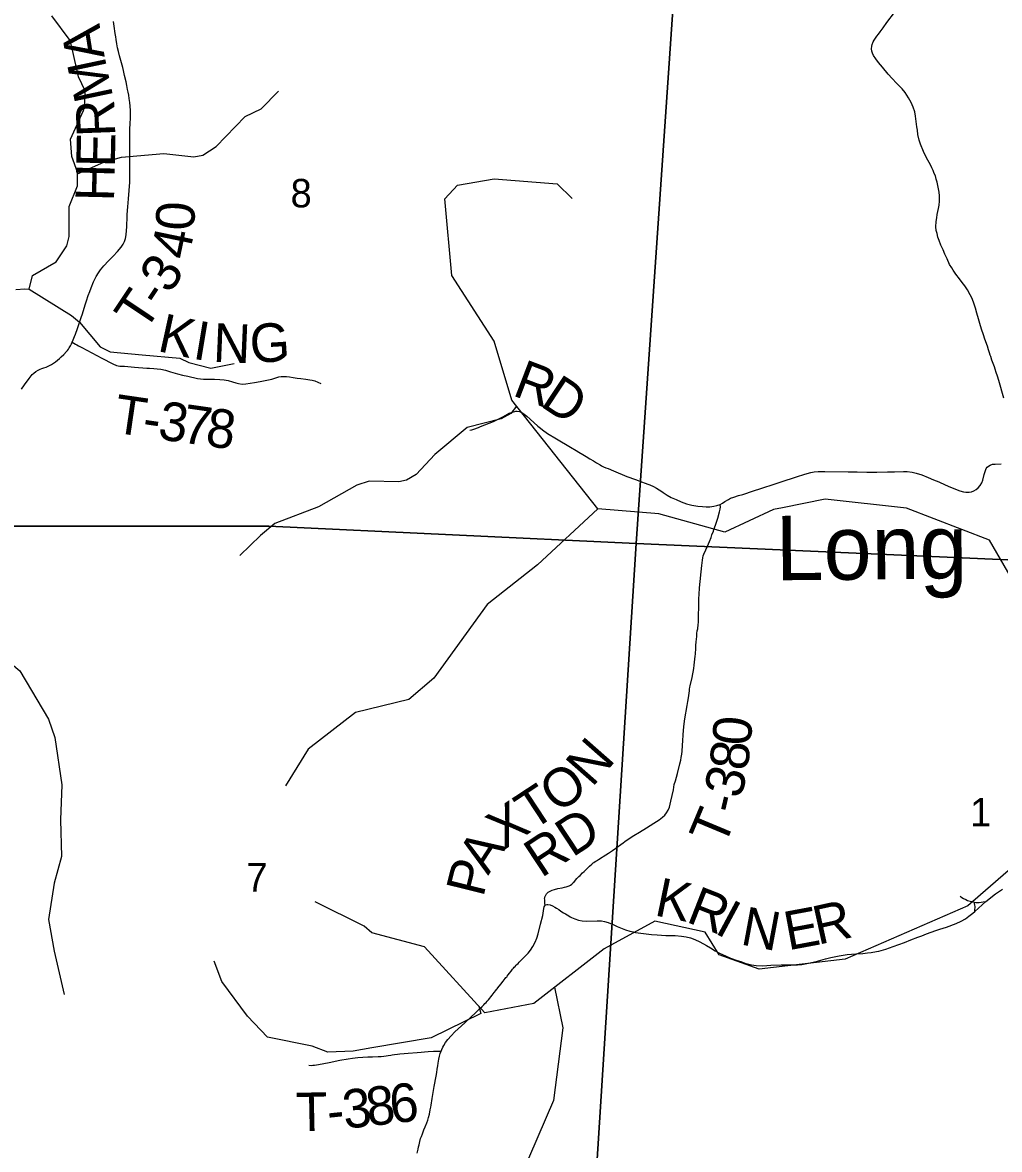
# Model space of a CAD drawing. Extents: x 21.4 to 65.3, y 4 to 26.
# Drawn here: x 24.436 to 25.873, y 20.591 to 22.248 of the extents above; entities that cross this region are included whole.
import ezdxf

# ---------------------------------------------------------------- set-up
doc = ezdxf.new("R2010")
doc.units = 0
for name, color, linetype in [('GM_X_County_Road', 7, 'Continuous'), ('GM_X_County_Road_Text', 7, 'Continuous'), ('GM_X_Minor_River', 7, 'Continuous'), ('GM_X_Minor_River_Text', 7, 'Continuous'), ('GM_X_Section', 7, 'Continuous'), ('GM_X_Section_Text', 7, 'Continuous'), ('GM_X_Township_Road', 7, 'Continuous'), ('GM_X_Township_Road_Text', 7, 'Continuous')]:
    doc.layers.add(name, color=color, linetype=linetype)

msp = doc.modelspace()

# ---------------------------------------------------------------- linework, layer by layer
at = {"layer": 'GM_X_County_Road'}
for points in [[(25.879, 21.6955), (25.8716, 21.7216), (25.8696, 21.7279), (25.8679, 21.7334), (25.8663, 21.7381), (25.8651, 21.7416), (25.8616, 21.7515), (25.8598, 21.7567), (25.8589, 21.759), (25.8577, 21.7625), (25.8563, 21.7666), (25.8548, 21.772), (25.851, 21.7823), (25.8489, 21.7887), (25.8462, 21.7969), (25.8437, 21.8055), (25.8419, 21.8121), (25.8393, 21.8208), (25.8372, 21.8281), (25.8344, 21.837), (25.832, 21.843), (25.8297, 21.8478), (25.8255, 21.8552), (25.8216, 21.861), (25.8179, 21.8656), (25.8136, 21.8713), (25.8084, 21.878), (25.8045, 21.8838), (25.8024, 21.8872), (25.7993, 21.8922), (25.7955, 21.9004), (25.7923, 21.9075), (25.7897, 21.9138), (25.7865, 21.9205), (25.7837, 21.9276), (25.7822, 21.9324), (25.7808, 21.9376), (25.7795, 21.9424), (25.7791, 21.9478), (25.7794, 21.9555), (25.7803, 21.9611), (25.7811, 21.9659), (25.782, 21.9701), (25.7829, 21.9747), (25.7837, 21.9795), (25.7842, 21.9853), (25.7842, 21.9931), (25.7838, 21.9986), (25.7827, 22.0062), (25.7808, 22.0133), (25.7797, 22.0175), (25.7783, 22.0224), (25.7768, 22.0262), (25.7753, 22.0303), (25.7732, 22.0343), (25.771, 22.0388), (25.7651, 22.0492), (25.7608, 22.0582), (25.7563, 22.0692), (25.7546, 22.0753), (25.7528, 22.0834), (25.7519, 22.0898), (25.7511, 22.0947), (25.7502, 22.1027), (25.7492, 22.1105), (25.748, 22.1168), (25.7459, 22.1236), (25.7428, 22.1306), (25.739, 22.1375), (25.7339, 22.1453), (25.7294, 22.1505), (25.7252, 22.1551), (25.7214, 22.1591), (25.715, 22.1659), (25.7091, 22.1723), (25.7007, 22.1822), (25.6948, 22.1894), (25.6906, 22.1948), (25.6874, 22.1996), (25.6857, 22.203), (25.6848, 22.2062), (25.6844, 22.2094), (25.6847, 22.2132), (25.6853, 22.2157), (25.6869, 22.2199), (25.6882, 22.2221), (25.6905, 22.2251), (25.6924, 22.2279), (25.6949, 22.231), (25.6972, 22.2345), (25.7017, 22.2405), (25.7072, 22.2481), (25.7183, 22.2629)], [(25.8363, 20.941), (25.8527, 20.9555), (25.8666, 20.9666), (25.877, 20.9734)], [(25.0517, 20.7355), (25.0528, 20.738), (25.0542, 20.7413), (25.0555, 20.7439), (25.058, 20.7482), (25.0614, 20.7524), (25.0665, 20.7581), (25.0717, 20.7637), (25.0864, 20.7768), (25.095, 20.7849), (25.1026, 20.792), (25.1083, 20.7976), (25.1119, 20.8012), (25.1145, 20.8037), (25.1161, 20.8054), (25.1177, 20.8071), (25.1193, 20.8088), (25.1204, 20.8101), (25.1212, 20.8109), (25.1231, 20.8131), (25.125, 20.8155), (25.1269, 20.8178), (25.1299, 20.8216), (25.1322, 20.8245), (25.1333, 20.826), (25.134, 20.8269), (25.1352, 20.8283), (25.1397, 20.834), (25.1429, 20.8384), (25.1459, 20.8421), (25.147, 20.8435), (25.1481, 20.8449), (25.1488, 20.8459), (25.1501, 20.8477), (25.1522, 20.8503), (25.1545, 20.8532), (25.1557, 20.8545), (25.1568, 20.8559), (25.1581, 20.8573), (25.1593, 20.8587), (25.1606, 20.86), (25.1622, 20.8618), (25.1631, 20.8627), (25.1648, 20.8644), (25.1666, 20.8662), (25.1703, 20.8701), (25.1749, 20.8747), (25.1795, 20.8796), (25.1832, 20.8839), (25.1866, 20.8891), (25.1898, 20.8956), (25.1923, 20.9017), (25.1944, 20.9081), (25.1979, 20.922), (25.2011, 20.935), (25.2029, 20.9452), (25.2034, 20.9477), (25.204, 20.9492), (25.2046, 20.9498)], [(25.2046, 20.9498), (25.2053, 20.9504), (25.2069, 20.9509), (25.2088, 20.9511), (25.212, 20.9505), (25.2156, 20.9489), (25.2188, 20.9472), (25.2215, 20.9457), (25.2246, 20.9436), (25.2279, 20.9413), (25.2318, 20.939), (25.2346, 20.9373), (25.2393, 20.9342), (25.2414, 20.9329), (25.2436, 20.9318), (25.2482, 20.9298), (25.2535, 20.9281), (25.2589, 20.9271), (25.2655, 20.9267), (25.2811, 20.9271), (25.2875, 20.9268), (25.2921, 20.9261), (25.2972, 20.9246), (25.3055, 20.9212), (25.3104, 20.9188), (25.3152, 20.9167), (25.3226, 20.9136), (25.3291, 20.9118), (25.3338, 20.9108), (25.3377, 20.9099), (25.3453, 20.9088), (25.3529, 20.9078), (25.361, 20.907), (25.3693, 20.9063), (25.3758, 20.9058), (25.382, 20.9056), (25.3879, 20.9054), (25.3958, 20.9053), (25.4049, 20.9045), (25.4121, 20.9036), (25.4185, 20.9019), (25.4248, 20.8996), (25.432, 20.8961), (25.4418, 20.8907), (25.4476, 20.8873), (25.4547, 20.8831), (25.4611, 20.8796), (25.4697, 20.8755), (25.4771, 20.8722), (25.4868, 20.8686), (25.4921, 20.867), (25.4983, 20.865), (25.508, 20.8624), (25.5148, 20.8615), (25.5248, 20.8611), (25.5366, 20.8616), (25.5515, 20.8622), (25.557, 20.8623), (25.5682, 20.8621), (25.5757, 20.8622), (25.5819, 20.8629), (25.5917, 20.8647), (25.605, 20.8679), (25.6098, 20.8693), (25.6167, 20.8711), (25.6248, 20.8732), (25.6369, 20.8757), (25.6488, 20.8774), (25.6612, 20.8783), (25.6719, 20.8791), (25.6787, 20.8798), (25.6841, 20.8803), (25.6916, 20.8819), (25.695, 20.8826), (25.7054, 20.8856), (25.7164, 20.8892), (25.7328, 20.8953), (25.7425, 20.899), (25.7525, 20.9029), (25.7584, 20.9052), (25.7655, 20.9078), (25.7724, 20.9105), (25.7792, 20.9128), (25.785, 20.9148), (25.7948, 20.9179), (25.809, 20.9232), (25.8163, 20.9264), (25.8226, 20.9302), (25.8275, 20.9337), (25.8333, 20.9384), (25.8363, 20.941)], [(25.0167, 20.5856), (25.0178, 20.5911), (25.0185, 20.5945), (25.0192, 20.5977), (25.0205, 20.6025), (25.0216, 20.6067), (25.0228, 20.6101), (25.0241, 20.6137), (25.0264, 20.6195), (25.0282, 20.6243), (25.0307, 20.6301), (25.0321, 20.6338), (25.0331, 20.6376), (25.0345, 20.6427), (25.0358, 20.6489), (25.0364, 20.6528), (25.0369, 20.656), (25.0385, 20.6656), (25.0413, 20.6832), (25.0442, 20.6987), (25.0452, 20.7041), (25.0459, 20.7091), (25.0468, 20.7138), (25.0475, 20.7179), (25.0485, 20.7237), (25.0494, 20.7279), (25.0505, 20.7318), (25.0517, 20.7355)]]:
    msp.add_lwpolyline(points, dxfattribs=at)
at = {"layer": 'GM_X_Minor_River'}
for points in [[(24.4265, 21.8553), (24.4398, 21.8565), (24.4462, 21.8561), (24.4511, 21.8759), (24.4856, 21.8961), (24.5012, 21.9197), (24.5046, 21.9334), (24.505, 21.9775), (24.5171, 22.0079), (24.5171, 22.028), (24.5088, 22.0512), (24.5069, 22.0767), (24.5259, 22.1189), (24.5278, 22.1254), (24.5282, 22.1474), (24.5187, 22.168), (24.5093, 22.2098), (24.5062, 22.2216), (24.4793, 22.258)], [(24.5171, 22.0254), (24.5556, 22.0428), (24.5819, 22.05), (24.6439, 22.0553), (24.6883, 22.0505), (24.7012, 22.053), (24.7211, 22.0656), (24.7636, 22.1099), (24.7869, 22.121), (24.8127, 22.1472)], [(25.2821, 21.5328), (25.1557, 21.6926), (25.1299, 21.7797), (25.0675, 21.8759), (25.0569, 21.9889), (25.0757, 22.0088), (25.1298, 22.0184), (25.2225, 22.0109), (25.2445, 21.9894)], [(24.4462, 21.8561), (24.5083, 21.817), (24.5199, 21.8073), (24.5506, 21.7711), (24.5649, 21.7637), (24.612, 21.7593), (24.6673, 21.7547), (24.6809, 21.7481), (24.7131, 21.74), (24.7474, 21.7468)], [(25.1627, 21.6838), (25.1543, 21.6732), (25.1401, 21.6654), (25.0898, 21.6524), (25.0422, 21.6128), (25.0152, 21.5835), (25.001, 21.575), (24.9895, 21.5725), (24.9459, 21.5738), (24.9279, 21.5676), (24.8716, 21.5361), (24.8071, 21.5115), (24.7863, 21.4939), (24.7559, 21.4643)], [(25.8903, 21.4308), (25.8577, 21.4867), (25.736, 21.5338), (25.6162, 21.5471), (25.5534, 21.5344), (25.5405, 21.5317), (25.4688, 21.4988), (25.372, 21.5256), (25.282, 21.5328), (25.1935, 21.4504), (25.1194, 21.3924), (25.0412, 21.2839), (25.0044, 21.2525), (24.926, 21.2335), (24.8561, 21.1794), (24.823, 21.1256)], [(24.3346, 21.3102), (24.3759, 21.3218), (24.4202, 21.3048), (24.4323, 21.2949), (24.4744, 21.2238), (24.4835, 21.1965), (24.4941, 21.1269), (24.4922, 21.0756), (24.4937, 21.0216), (24.483, 20.9824), (24.4743, 20.9292), (24.4826, 20.8824), (24.4974, 20.8189)], [(26.1634, 21.1477), (26.0593, 21.1142), (25.9946, 21.0666), (25.9113, 21.0233), (25.8261, 20.9493), (25.6456, 20.8706), (25.5194, 20.8558), (25.4603, 20.877), (25.4397, 20.9106), (25.3659, 20.9266), (25.2916, 20.8861), (25.1879, 20.8054), (25.1159, 20.7919), (25.027, 20.889), (24.95, 20.9096), (24.9385, 20.919), (24.8667, 20.9548)], [(25.1071, 20.8015), (25.1103, 20.7906), (25.0372, 20.7548), (24.9496, 20.7404), (24.9222, 20.7354), (24.8853, 20.734), (24.8623, 20.7427), (24.7964, 20.7562), (24.7672, 20.787), (24.7292, 20.8376), (24.7182, 20.8678)], [(25.2185, 20.8293), (25.2305, 20.7698), (25.2167, 20.663), (25.1342, 20.4706), (25.1208, 20.42)]]:
    msp.add_lwpolyline(points, dxfattribs=at)
at = {"layer": 'GM_X_Section'}
for points in [[(24.3505, 22.5376), (24.828, 22.5152), (25.4085, 22.5025), (25.3384, 21.4821), (24.7985, 21.5074), (24.2858, 21.5075), (24.3136, 21.9252), (24.3404, 22.3383)], [(25.4085, 22.5025), (26.4597, 22.4573), (26.4491, 22.292), (26.4111, 21.6607), (26.3977, 21.4352), (25.3384, 21.4821)], [(25.3384, 21.4821), (25.275, 20.4836), (24.2227, 20.5192), (24.2858, 21.5075), (24.7985, 21.5074)], [(26.3977, 21.4352), (26.3809, 21.1738), (26.3352, 20.4317), (25.2871, 20.4832), (25.275, 20.4836), (25.3384, 21.4821)]]:
    msp.add_lwpolyline(points, close=True, dxfattribs=at)
at = {"layer": 'GM_X_Township_Road'}
for points in [[(24.4349, 21.7091), (24.4393, 21.7151), (24.446, 21.7247), (24.4506, 21.7304), (24.4529, 21.7326), (24.4556, 21.7347), (24.4593, 21.7368), (24.4621, 21.7381), (24.4645, 21.7393), (24.4677, 21.7405), (24.4708, 21.7413), (24.4751, 21.7433), (24.4788, 21.7453), (24.4847, 21.7489), (24.4878, 21.7516), (24.4905, 21.754), (24.4932, 21.7565), (24.497, 21.7599), (24.501, 21.7644), (24.5023, 21.7659), (24.5039, 21.7678), (24.505, 21.7696), (24.5067, 21.7725), (24.5083, 21.7757), (24.5092, 21.7778), (24.5108, 21.7813), (24.5127, 21.7864), (24.514, 21.7899), (24.517, 21.7981), (24.5207, 21.8086), (24.5226, 21.8144), (24.5244, 21.8198), (24.5283, 21.8329), (24.5303, 21.839), (24.5327, 21.8464), (24.535, 21.8525), (24.5371, 21.858), (24.5407, 21.8666), (24.5444, 21.8744), (24.5478, 21.8802), (24.5507, 21.8842), (24.5558, 21.8904), (24.5625, 21.8977), (24.5695, 21.9047), (24.5759, 21.9114), (24.5811, 21.9177), (24.5842, 21.9223), (24.5862, 21.9262), (24.5876, 21.9304), (24.5885, 21.936), (24.5892, 21.9422), (24.5895, 21.9474), (24.5897, 21.9527), (24.59, 21.9583), (24.5901, 21.9626), (24.5903, 21.9651), (24.5908, 21.9714), (24.5912, 21.9768), (24.592, 21.9889), (24.5938, 22.0132), (24.5942, 22.0334), (24.5942, 22.0402), (24.594, 22.0506), (24.5939, 22.0543), (24.5938, 22.0648), (24.5939, 22.0822), (24.5941, 22.0909), (24.5945, 22.1001), (24.595, 22.1068), (24.5952, 22.1123), (24.595, 22.1187), (24.5946, 22.1252), (24.5941, 22.1307), (24.5931, 22.1362), (24.5924, 22.1411), (24.5914, 22.1459), (24.5907, 22.1496), (24.5896, 22.1557), (24.5885, 22.1611), (24.5863, 22.1704), (24.5847, 22.1775), (24.5836, 22.1821), (24.5828, 22.1855), (24.5788, 22.1989), (24.5771, 22.2056), (24.5759, 22.211), (24.5749, 22.2165), (24.5738, 22.2232), (24.5732, 22.2268), (24.5726, 22.2318), (24.5711, 22.2426), (24.5702, 22.2495)], [(24.5092, 21.7778), (24.5143, 21.7751), (24.5159, 21.7743), (24.5185, 21.7728), (24.5234, 21.7702), (24.5381, 21.7622), (24.5526, 21.7547), (24.5688, 21.7462), (24.5746, 21.7438), (24.5792, 21.7429), (24.5861, 21.7425), (24.601, 21.7411), (24.6189, 21.7399), (24.6227, 21.7397), (24.6293, 21.7392), (24.634, 21.7387), (24.6397, 21.7381), (24.6463, 21.7368), (24.654, 21.7346), (24.6642, 21.7315), (24.6712, 21.7295), (24.6795, 21.7281), (24.6935, 21.7248), (24.7024, 21.7235), (24.7103, 21.7234), (24.7186, 21.7234), (24.7264, 21.7232), (24.7327, 21.7227), (24.7384, 21.7216), (24.7451, 21.7196), (24.7498, 21.7182), (24.7539, 21.7173), (24.7591, 21.7164), (24.7647, 21.7167), (24.7708, 21.7175), (24.7775, 21.7188), (24.7856, 21.7201), (24.7952, 21.7221), (24.8028, 21.7238), (24.8085, 21.7255), (24.8133, 21.7268), (24.8166, 21.7274), (24.82, 21.7277), (24.8245, 21.7274), (24.8289, 21.7268), (24.8343, 21.726), (24.8398, 21.7252), (24.8456, 21.7244), (24.8529, 21.7235), (24.8585, 21.7227), (24.8622, 21.7221), (24.8658, 21.7211), (24.8704, 21.7194), (24.875, 21.7173)], [(25.0941, 21.6485), (25.097, 21.6491), (25.1, 21.65), (25.1064, 21.6525), (25.1097, 21.6538), (25.1288, 21.6615), (25.1432, 21.6687), (25.1519, 21.6735), (25.1565, 21.6753), (25.1613, 21.6765), (25.1637, 21.6767), (25.1667, 21.676), (25.1702, 21.6746), (25.174, 21.6722), (25.1779, 21.6691), (25.1825, 21.6649), (25.1939, 21.6544), (25.1978, 21.6513), (25.2007, 21.6489), (25.2083, 21.6436), (25.2211, 21.636), (25.2419, 21.6236), (25.25, 21.6189), (25.2542, 21.6164), (25.26, 21.613), (25.2649, 21.6101), (25.2704, 21.6066), (25.2757, 21.6033), (25.2801, 21.6005), (25.2854, 21.5974), (25.2877, 21.5962), (25.2903, 21.5948), (25.2937, 21.5934), (25.2972, 21.592), (25.3052, 21.5886), (25.3247, 21.5807), (25.3375, 21.576), (25.3462, 21.5728), (25.3515, 21.5708), (25.3555, 21.5693), (25.3584, 21.5682), (25.3641, 21.5659), (25.3685, 21.5635), (25.3721, 21.5611), (25.3745, 21.5594), (25.3782, 21.5567), (25.3839, 21.553), (25.3899, 21.5498), (25.3974, 21.5465), (25.4045, 21.5433), (25.4125, 21.5403), (25.4203, 21.5385), (25.4289, 21.537), (25.4361, 21.5363), (25.4414, 21.536), (25.4466, 21.5361), (25.4525, 21.5369), (25.4572, 21.538), (25.4619, 21.5395)], [(25.4619, 21.5395), (25.4655, 21.5413), (25.469, 21.5435), (25.474, 21.5466), (25.4772, 21.5484), (25.4818, 21.5501), (25.4888, 21.5523), (25.4953, 21.5542), (25.4995, 21.5555), (25.5066, 21.5577), (25.5125, 21.5597), (25.5201, 21.5622), (25.5443, 21.5703), (25.5514, 21.5726), (25.5744, 21.58), (25.5863, 21.5838), (25.5951, 21.5865), (25.5999, 21.5874), (25.606, 21.5878), (25.6159, 21.5879), (25.6501, 21.5874), (25.6632, 21.5872), (25.6774, 21.5869), (25.6923, 21.5868), (25.7079, 21.5871), (25.7183, 21.5874), (25.7315, 21.5878), (25.737, 21.5876), (25.7443, 21.5867), (25.7503, 21.5853), (25.7586, 21.5827), (25.7678, 21.5792), (25.7757, 21.5757), (25.7832, 21.5724), (25.7926, 21.5683), (25.8008, 21.5647), (25.8141, 21.5594), (25.8196, 21.5578), (25.8233, 21.5573), (25.8278, 21.5574), (25.8315, 21.5581), (25.8351, 21.5595), (25.8384, 21.5614), (25.8413, 21.5638), (25.8442, 21.5672), (25.8465, 21.5711), (25.8481, 21.5751), (25.8503, 21.5836), (25.852, 21.5895), (25.8532, 21.5922), (25.8546, 21.5942), (25.8563, 21.5958), (25.8588, 21.5973), (25.8623, 21.5984), (25.8665, 21.5988), (25.8752, 21.599)], [(25.2046, 20.9498), (25.2044, 20.9524), (25.204, 20.958), (25.2039, 20.9599), (25.2041, 20.9609), (25.2044, 20.9621), (25.2047, 20.9631), (25.2051, 20.9639), (25.2067, 20.9666), (25.2091, 20.969), (25.2122, 20.9709), (25.2149, 20.9721), (25.2184, 20.9733), (25.2231, 20.9745), (25.2296, 20.9757), (25.2331, 20.9764), (25.2357, 20.977), (25.2398, 20.9785), (25.2421, 20.9797), (25.2441, 20.9811), (25.2452, 20.9825), (25.246, 20.9833), (25.2476, 20.9851), (25.2513, 20.9891), (25.2543, 20.9922), (25.2561, 20.9939), (25.2596, 20.9974), (25.2619, 20.9995), (25.2699, 21.0072), (25.2731, 21.0102), (25.2753, 21.0122), (25.2763, 21.0128), (25.2782, 21.0142), (25.2803, 21.0154), (25.2833, 21.0174), (25.2885, 21.0206), (25.2901, 21.0215), (25.2979, 21.0265), (25.3035, 21.0303), (25.3085, 21.0339), (25.3105, 21.0353), (25.316, 21.0392), (25.3193, 21.0418), (25.3216, 21.0436), (25.3282, 21.048), (25.3348, 21.0524), (25.3431, 21.0575), (25.3534, 21.0639), (25.3642, 21.0708), (25.3721, 21.0758), (25.3773, 21.0793), (25.3805, 21.0824), (25.3832, 21.0859), (25.3854, 21.0897), (25.3873, 21.0944), (25.3884, 21.0985), (25.3896, 21.1028), (25.3914, 21.1115), (25.3932, 21.1198), (25.3945, 21.1273), (25.3965, 21.1331), (25.3992, 21.1439), (25.4027, 21.1577), (25.4039, 21.1635), (25.4047, 21.1674), (25.4054, 21.1723), (25.406, 21.1767), (25.4066, 21.1847), (25.4081, 21.2076), (25.409, 21.2168), (25.4099, 21.2241), (25.4133, 21.2436), (25.4143, 21.2494), (25.4153, 21.2552), (25.4167, 21.2651), (25.417, 21.2677), (25.4174, 21.2705), (25.4179, 21.2726), (25.4206, 21.285), (25.4231, 21.2979), (25.4238, 21.3031), (25.4254, 21.3164), (25.4258, 21.319), (25.4259, 21.3219), (25.426, 21.325), (25.4262, 21.3284), (25.4263, 21.3321), (25.4266, 21.3371), (25.427, 21.3414), (25.4274, 21.3454), (25.4278, 21.3494), (25.4283, 21.3535), (25.4289, 21.3566), (25.4296, 21.363), (25.4299, 21.3659), (25.43, 21.3718), (25.4306, 21.3931), (25.4308, 21.401), (25.4311, 21.4068), (25.4318, 21.4165), (25.4349, 21.4497), (25.4358, 21.4575), (25.4364, 21.461), (25.437, 21.4636), (25.438, 21.4663), (25.4408, 21.4725), (25.4435, 21.4781), (25.4462, 21.4851), (25.4485, 21.4909), (25.4499, 21.4949), (25.4519, 21.5), (25.4528, 21.5024), (25.4551, 21.5088), (25.4571, 21.5146), (25.4587, 21.5194), (25.4612, 21.5283), (25.462, 21.5323), (25.4622, 21.5359), (25.4619, 21.5395)], [(25.8146, 20.9633), (25.8173, 20.9613), (25.8198, 20.9597), (25.8229, 20.9582), (25.8258, 20.9571), (25.8296, 20.9561), (25.833, 20.9553), (25.8352, 20.9547), (25.8379, 20.9542), (25.8405, 20.954), (25.8428, 20.9542), (25.8456, 20.9546), (25.8485, 20.9549), (25.8527, 20.9555)], [(25.8363, 20.941), (25.8365, 20.9439), (25.8367, 20.9465), (25.8367, 20.9483), (25.8366, 20.9499), (25.8361, 20.9523), (25.8352, 20.9547)], [(24.857, 20.7147), (24.8609, 20.7145), (24.8633, 20.7146), (24.8657, 20.7148), (24.8712, 20.7156), (24.8871, 20.7185), (24.9029, 20.7219), (24.9152, 20.7243), (24.9213, 20.7253), (24.9293, 20.7262), (24.9441, 20.7268), (24.951, 20.7268), (24.9589, 20.7273), (24.9634, 20.7277), (24.9675, 20.728), (24.9708, 20.7283), (24.9739, 20.7288), (24.9775, 20.7294), (24.9799, 20.7298), (24.9833, 20.7304), (24.9873, 20.731), (24.9912, 20.7314), (24.9972, 20.732), (25.0034, 20.7324), (25.0167, 20.7336), (25.0221, 20.734), (25.0272, 20.7343), (25.0326, 20.7347), (25.0404, 20.7352), (25.0468, 20.7354), (25.0517, 20.7355)]]:
    msp.add_lwpolyline(points, dxfattribs=at)

# ---------------------------------------------------------------- texts
at = {"layer": 'GM_X_County_Road_Text'}
for s, rotation, p in [('K', 348.4693, (25.3637, 20.9354)), ('R', 338.6244, (25.4103, 20.9261)), ('I', 331.7904, (25.4521, 20.9099)), ('E', 10.5457, (25.5618, 20.8835)), ('R', 12.5034, (25.6056, 20.8916)), ('N', 349.4188, (25.4903, 20.8926))]:
    msp.add_text(s, height=0.0568, rotation=rotation, dxfattribs=at).set_placement(p)
at = {"layer": 'GM_X_Minor_River_Text'}
msp.add_text('Long', height=0.0947, rotation=0.5112, dxfattribs=at).set_placement((25.544, 21.4278))
at = {"layer": 'GM_X_Section_Text'}
for s, p in [('8', (24.8303, 21.9762)), ('1', (25.8295, 21.0658)), ('7', (24.7653, 20.9701))]:
    msp.add_text(s, height=0.0419, rotation=0, dxfattribs=at).set_placement(p)
at = {"layer": 'GM_X_Township_Road_Text'}
for s, height, rotation, p in [('A', 0.0568, 98.976, (24.5571, 22.1976)), ('M', 0.0568, 101.9764, (24.5698, 22.1381)), ('R', 0.0568, 92.1144, (24.5728, 22.0809)), ('E', 0.0568, 88.7221, (24.5719, 22.0347)), ('H', 0.0568, 88.6192, (24.5707, 21.9846)), ('0', 0.0568, 86.9958, (24.6883, 21.9411)), ('4', 0.0568, 78.2462, (24.68, 21.8975)), ('3', 0.0568, 57.8282, (24.6531, 21.8475)), ('T', 0.0568, 56.159, (24.6155, 21.7912)), ('-', 0.0568, 56.2662, (24.6393, 21.8266)), ('K', 0.0568, 347.5755, (24.633, 21.7653)), ('I', 0.0568, 350.5159, (24.685, 21.7539)), ('N', 0.0568, 357.5849, (24.7156, 21.7493)), ('G', 0.0568, 3.4121, (24.7719, 21.7472)), ('R', 0.0568, 339.131, (25.1549, 21.7003)), ('D', 0.0568, 326.4024, (25.1956, 21.6852)), ('T', 0.0568, 351.6566, (24.5685, 21.6454)), ('3', 0.0568, 351.7154, (24.6337, 21.6358)), ('7', 0.0568, 351.8574, (24.6685, 21.6308)), ('8', 0.0568, 352.3329, (24.7037, 21.6257)), ('-', 0.0568, 351.663, (24.6106, 21.6392)), ('0', 0.0568, 85.0182, (25.5064, 21.1834)), ('N', 0.0568, 48.6455, (25.2735, 21.1223)), ('8', 0.0568, 83.1109, (25.502, 21.1466)), ('O', 0.0568, 36.3398, (25.2235, 21.0837)), ('3', 0.0568, 76.2446, (25.4923, 21.1053)), ('T', 0.0568, 33.3311, (25.1853, 21.0585)), ('X', 0.0568, 33.7896, (25.1438, 21.0307)), ('T', 0.0568, 67.3056, (25.4675, 21.0336)), ('-', 0.0568, 76.9909, (25.4871, 21.0827)), ('RD', 0.05682, 33.4162, (25.1989, 20.9893)), ('A', 0.0568, 56.9707, (25.1208, 20.9931)), ('P', 0.0568, 76.0358, (25.1135, 20.9605)), ('8', 0.0568, 6.4735, (24.9445, 20.6249)), ('6', 0.0568, 6.5027, (24.979, 20.6288)), ('T', 0.0568, 1.2332, (24.8389, 20.6173)), ('3', 0.0568, 6.3814, (24.9099, 20.621)), ('-', 0.0568, 5.978, (24.8864, 20.6186))]:
    msp.add_text(s, height=height, rotation=rotation, dxfattribs=at).set_placement(p)

doc.saveas('drawing.dxf')
